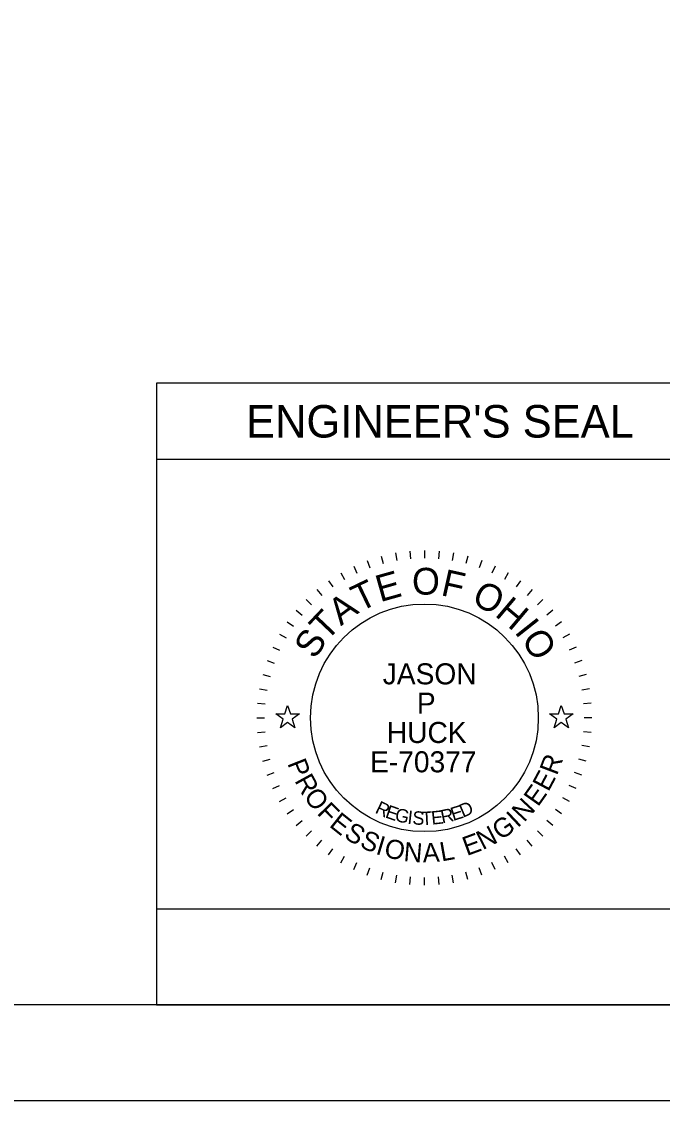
# Model space of a CAD drawing. Extents: x 0 to 34, y 0 to 22.
# Drawn here: x 6.64 to 9.99, y 0 to 5.64 of the extents above; entities that cross this region are included whole.
import ezdxf

# ---------------------------------------------------------------- set-up
doc = ezdxf.new("R2010")
doc.units = 0
for name, color, linetype in [('Default', 7, 'Continuous'), ('SH_Border', 7, 'Continuous'), ('SH_Cut_Line', 7, 'Continuous'), ('SH_Data', 7, 'Continuous')]:
    doc.layers.add(name, color=color, linetype=linetype)

msp = doc.modelspace()

# ---------------------------------------------------------------- linework, layer by layer
at = {"layer": 'Default'}
for points in [[(7.9736, 2.02), (8.0205, 2.02), (8.035, 2.0645), (8.0495, 2.02), (8.0964, 2.02), (8.0585, 1.9924), (8.073, 1.9478), (8.035, 1.9754), (7.997, 1.9478), (8.0115, 1.9924)], [(9.4036, 2.02), (9.4505, 2.02), (9.465, 2.0645), (9.4795, 2.02), (9.5264, 2.02), (9.4885, 1.9924), (9.503, 1.9478), (9.465, 1.9754), (9.427, 1.9478), (9.4415, 1.9924)]]:
    msp.add_lwpolyline(points, close=True, dxfattribs=at)
at = {"layer": 'SH_Border'}
msp.add_lwpolyline([(1.5, 21.5), (33.5, 21.5), (33.5, 0.5), (1.5, 0.5)], close=True, dxfattribs=at)
at = {"layer": 'SH_Cut_Line'}
msp.add_lwpolyline([(0, 0), (34, 0), (34, 22), (0, 22)], close=True, dxfattribs=at)
at = {"layer": 'SH_Data'}
for p, q in [((10.15, 3.75), (7.35, 3.75)), ((7.35, 3.75), (7.35, 0.5)), ((10.15, 3.35), (7.35, 3.35)), ((8.4507, 2.8222), (8.4644, 2.7846)), ((8.5235, 2.8452), (8.5339, 2.8065)), ((8.5981, 2.8617), (8.605, 2.8223)), ((8.6737, 2.8717), (8.6772, 2.8318)), ((8.75, 2.875), (8.75, 2.835)), ((8.8263, 2.8717), (8.8228, 2.8318)), ((8.9019, 2.8617), (8.895, 2.8223)), ((8.9765, 2.8452), (8.9661, 2.8065)), ((9.0493, 2.8222), (9.0356, 2.7846)), ((8.3802, 2.793), (8.3971, 2.7568)), ((9.1198, 2.793), (9.1029, 2.7568)), ((8.2481, 2.7168), (8.2711, 2.684)), ((8.3125, 2.7578), (8.3325, 2.7231)), ((9.1875, 2.7578), (9.1675, 2.7231)), ((9.2519, 2.7168), (9.2289, 2.684)), ((8.1876, 2.6703), (8.2133, 2.6396)), ((9.3124, 2.6703), (9.2867, 2.6396)), ((8.1313, 2.6187), (8.1596, 2.5904)), ((9.3687, 2.6187), (9.3404, 2.5904)), ((8.0797, 2.5624), (8.1104, 2.5367)), ((9.4203, 2.5624), (9.3896, 2.5367)), ((8.0332, 2.5019), (8.066, 2.4789)), ((9.4668, 2.5019), (9.434, 2.4789)), ((7.9922, 2.4375), (8.0269, 2.4175)), ((9.5078, 2.4375), (9.4731, 2.4175)), ((7.957, 2.3698), (7.9932, 2.3529)), ((9.543, 2.3698), (9.5068, 2.3529)), ((7.9278, 2.2993), (7.9654, 2.2856)), ((9.5722, 2.2993), (9.5346, 2.2856)), ((7.9048, 2.2265), (7.9435, 2.2161)), ((9.5952, 2.2265), (9.5565, 2.2161)), ((7.8883, 2.1519), (7.9277, 2.145)), ((9.6117, 2.1519), (9.5723, 2.145)), ((7.8783, 2.0763), (7.9182, 2.0728)), ((9.6217, 2.0763), (9.5818, 2.0728)), ((7.875, 2), (7.915, 2)), ((9.625, 2), (9.585, 2)), ((7.8783, 1.9237), (7.9182, 1.9272)), ((9.6217, 1.9237), (9.5818, 1.9272)), ((7.8883, 1.8481), (7.9277, 1.855)), ((9.6117, 1.8481), (9.5723, 1.855)), ((7.9048, 1.7735), (7.9435, 1.7839)), ((9.5952, 1.7735), (9.5565, 1.7839)), ((7.9278, 1.7007), (7.9654, 1.7144)), ((9.5722, 1.7007), (9.5346, 1.7144)), ((7.957, 1.6302), (7.9932, 1.6471)), ((9.543, 1.6302), (9.5068, 1.6471)), ((7.9922, 1.5625), (8.0269, 1.5825)), ((9.5078, 1.5625), (9.4731, 1.5825)), ((8.0332, 1.4981), (8.066, 1.5211)), ((9.4668, 1.4981), (9.434, 1.5211)), ((8.0797, 1.4376), (8.1104, 1.4633)), ((9.4203, 1.4376), (9.3896, 1.4633)), ((8.1313, 1.3813), (8.1596, 1.4096)), ((8.1876, 1.3297), (8.2133, 1.3604)), ((9.3124, 1.3297), (9.2867, 1.3604)), ((9.3687, 1.3813), (9.3404, 1.4096)), ((8.2481, 1.2832), (8.2711, 1.316)), ((9.2519, 1.2832), (9.2289, 1.316)), ((8.3125, 1.2422), (8.3325, 1.2769)), ((8.3802, 1.207), (8.3971, 1.2432)), ((9.1198, 1.207), (9.1029, 1.2432)), ((9.1875, 1.2422), (9.1675, 1.2769)), ((8.4507, 1.1778), (8.4644, 1.2154)), ((8.5235, 1.1548), (8.5339, 1.1935)), ((8.9765, 1.1548), (8.9661, 1.1935)), ((9.0493, 1.1778), (9.0356, 1.2154)), ((8.5981, 1.1383), (8.605, 1.1777)), ((8.6737, 1.1283), (8.6772, 1.1682)), ((8.75, 1.125), (8.75, 1.165)), ((8.8263, 1.1283), (8.8228, 1.1682)), ((8.9019, 1.1383), (8.895, 1.1777)), ((10.15, 0.5), (7.35, 0.5))]:
    msp.add_line(p, q, dxfattribs=at)
msp.add_lwpolyline([(10.15, 0.5), (10.15, 1), (7.35, 1), (7.35, 0.5)], close=True, dxfattribs=at)
msp.add_circle((8.75, 2), 0.595, dxfattribs=at)

# ---------------------------------------------------------------- texts
for s, height, p in [("ENGINEER'S SEAL", 0.17, (7.8176, 3.465)), ('JASON', 0.11, (8.5321, 2.1749)), ('P', 0.11, (8.7105, 2.0216)), ('HUCK', 0.11, (8.5535, 1.8684)), ('E-70377', 0.11, (8.4659, 1.7151))]:
    msp.add_text(s, height=height, dxfattribs=at).set_placement(p)
for s, height, rotation, p in [('E', 0.14, 15.7571, (8.5184, 2.6038)), ('O', 0.14, 359.7812, (8.6847, 2.6443)), ('F', 0.14, 347.4362, (8.8311, 2.6417)), ('T', 0.14, 25.7167, (8.4116, 2.5518)), ('O', 0.14, 332.2586, (8.9898, 2.6015)), ('A', 0.14, 36.4747, (8.3134, 2.4781)), ('H', 0.14, 319.9136, (9.1132, 2.5361)), ('T', 0.14, 46.4344, (8.2383, 2.3964)), ('I', 0.14, 308.367, (9.2165, 2.4483)), ('S', 0.14, 57.1924, (8.1781, 2.3014)), ('O', 0.14, 303.1491, (9.2521, 2.4089)), ('R', 0.1, 69.2322, (9.4419, 1.6954)), ('P', 0.1, 291.494, (8.0323, 1.7621)), ('R', 0.1, 298.7311, (8.069, 1.6717)), ('E', 0.1, 61.9951, (9.3976, 1.6098)), ('E', 0.1, 54.758, (9.3433, 1.5314)), ('O', 0.1, 306.4666, (8.1155, 1.5883)), ('N', 0.1, 47.0224, (9.2702, 1.4508)), ('F', 0.1, 314.7068, (8.1843, 1.4983)), ('R', 0.07, 334.487, (8.4875, 1.5051)), ('E', 0.07, 341.04, (8.5406, 1.4801)), ('G', 0.07, 347.4752, (8.5914, 1.4618)), ('R', 0.07, 11.9184, (8.8425, 1.4474)), ('E', 0.07, 17.6836, (8.8998, 1.4602)), ('D', 0.07, 23.3052, (8.951, 1.477)), ('E', 0.1, 321.4393, (8.2478, 1.4348)), ('I', 0.07, 353.7858, (8.6591, 1.4468)), ('S', 0.07, 356.8926, (8.6858, 1.4429)), ('T', 0.07, 3.0061, (8.7357, 1.4387)), ('E', 0.07, 6.0117, (8.7889, 1.4412)), ('G', 0.1, 35.0469, (9.1481, 1.357)), ('I', 0.1, 43.287, (9.2368, 1.4214)), ('S', 0.1, 328.6764, (8.3243, 1.3752)), ('N', 0.1, 27.3113, (9.0545, 1.3075)), ('S', 0.1, 335.9134, (8.4064, 1.3266)), ('I', 0.1, 343.1505, (8.4906, 1.2897)), ('O', 0.1, 346.8859, (8.5339, 1.2751)), ('E', 0.1, 20.0742, (8.9712, 1.277)), ('N', 0.1, 355.1261, (8.6388, 1.2517)), ('A', 0.1, 2.8617, (8.7423, 1.2437)), ('L', 0.1, 10.0987, (8.8394, 1.249))]:
    msp.add_text(s, height=height, rotation=rotation, dxfattribs=at).set_placement(p)

doc.saveas('drawing.dxf')
